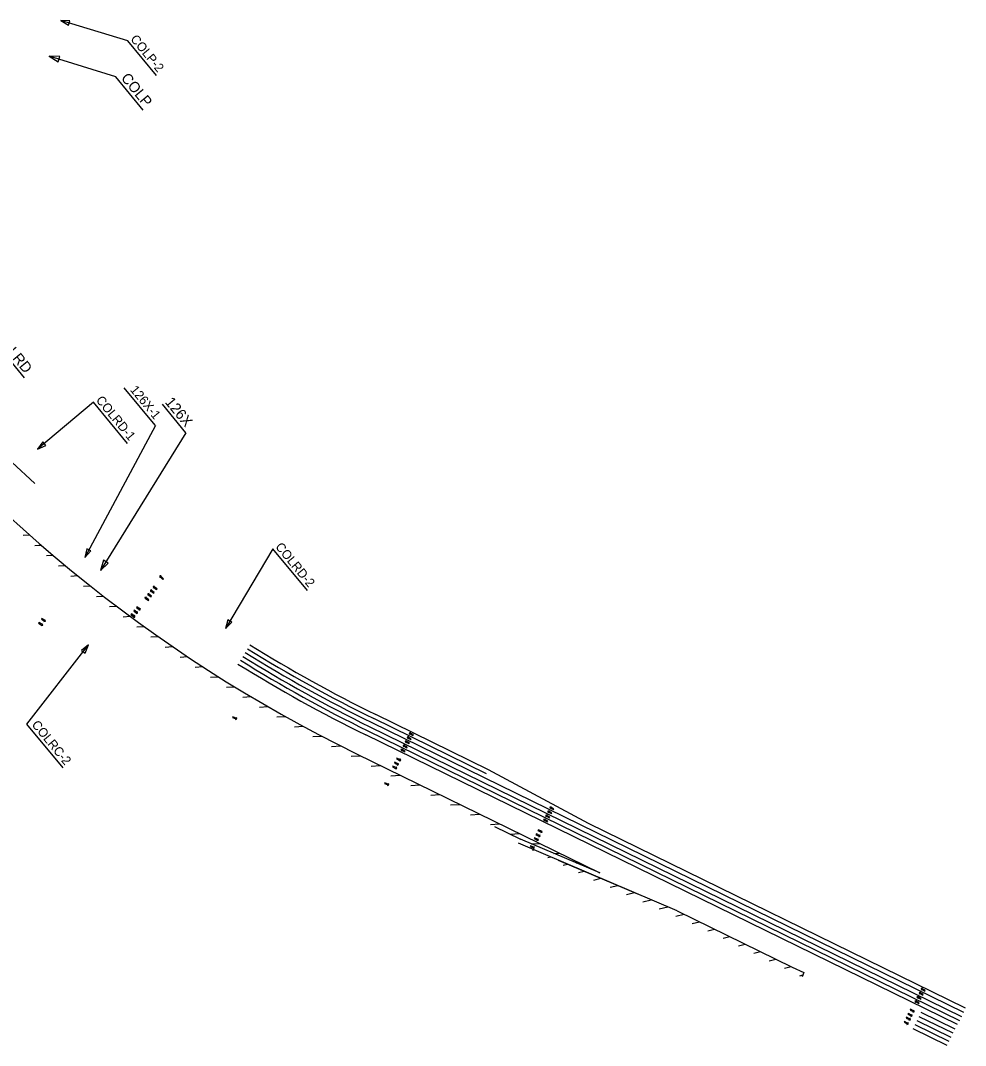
# Model space of a CAD drawing. Extents: x 1966356 to 1974207, y 790684 to 800034.
# Drawn here: x 1971705 to 1974207, y 793957 to 796672 of the extents above; entities that cross this region are included whole.
import ezdxf

# ---------------------------------------------------------------- set-up
doc = ezdxf.new("R2010")
doc.units = 0
for name, color, linetype in [('RD_EX_Pavement_Markings', 7, 'Continuous'), ('RD_PD_ALT5_LnLine', 7, 'Continuous'), ('RD_TX_RoadID', 7, 'Continuous')]:
    doc.layers.add(name, color=color, linetype=linetype)

msp = doc.modelspace()

# ---------------------------------------------------------------- linework, layer by layer
at = {"layer": 'RD_EX_Pavement_Markings'}
for p, q in [((1972944.6, 794687.2), (1972645.7, 794833.6)), ((1972635.1, 794812), (1974201.9, 794044.9)), ((1972939.3, 794676.4), (1972640.4, 794822.8)), ((1974186, 794012.5), (1972619.3, 794779.7)), ((1972624.6, 794790.5), (1974191.3, 794023.3)), ((1972629.9, 794801.2), (1974196.6, 794034.1)), ((1973208.8, 794544.5), (1972944.6, 794687.2)), ((1974207.1, 794055.6), (1973208.8, 794544.5)), ((1974169.3, 793978.4), (1974079.5, 794022.4)), ((1974174.6, 793989.2), (1974084.8, 794033.2)), ((1974179.9, 794000), (1974090.1, 794043.9)), ((1974158.8, 793956.9), (1974069, 794000.8)), ((1974164, 793967.6), (1974074.2, 794011.6))]:
    msp.add_line(p, q, dxfattribs=at)
for radius in [3776.7, 3764.7, 3752.7, 3800.7, 3788.7, 3812.7]:
    msp.add_arc((1974296, 798203.9), radius, 238.0979, 243.9112, dxfattribs=at)
at = {"layer": 'RD_PD_ALT5_LnLine'}
for p, q in [((1971712.1, 795308.5), (1971729, 795309.5)), ((1971742.9, 795281.3), (1971760, 795282.4)), ((1971774.3, 795254.2), (1971791.5, 795255.3)), ((1971806.3, 795227.1), (1971823.7, 795228.2)), ((1971839, 795200.1), (1971856.6, 795201.2)), ((1971872.4, 795173.1), (1971890.2, 795174.2)), ((1971906.4, 795146.2), (1971924.5, 795147.3)), ((1971941.3, 795119.3), (1971959.6, 795120.4)), ((1971976.9, 795092.4), (1971995.5, 795093.6)), ((1972013.3, 795065.6), (1972032.1, 795066.8)), ((1972050.5, 795038.8), (1972069.6, 795040)), ((1972088.6, 795012.1), (1972108.1, 795013.3)), ((1972127.7, 794985.5), (1972147.4, 794986.7)), ((1972167.7, 794958.9), (1972187.7, 794960.2)), ((1972208.7, 794932.4), (1972229.1, 794933.7)), ((1972250.7, 794905.9), (1972271.5, 794907.2)), ((1972293.9, 794879.6), (1972315.1, 794880.9)), ((1972338.3, 794853.2), (1972359.8, 794854.6)), ((1972383.9, 794827), (1972405.9, 794828.4)), ((1972430.8, 794800.8), (1972453.3, 794802.2)), ((1972479.2, 794774.8), (1972502.2, 794776.2)), ((1972529.1, 794748.8), (1972552.7, 794750.3)), ((1972594.7, 794729.4), (1973239.1, 794413.9)), ((1972580.6, 794722.9), (1972604.8, 794724.4)), ((1972633.3, 794697.1), (1972657.5, 794698.6)), ((1972686, 794671.3), (1972710.2, 794672.8)), ((1972738.6, 794645.5), (1972762.9, 794647)), ((1972791.3, 794619.7), (1972815.6, 794621.2)), ((1972844, 794593.9), (1972868.3, 794595.4)), ((1972896.7, 794568.1), (1972920.9, 794569.6)), ((1972949.4, 794542.3), (1972973.6, 794543.8)), ((1972960.6, 794536.9), (1973028.9, 794503.4)), ((1973002.1, 794516.5), (1973026.3, 794518)), ((1973444.2, 794313.4), (1973024, 794492.5)), ((1973239.1, 794413.9), (1973028.7, 794503.5)), ((1973058.1, 794490.9), (1973079, 794492.2)), ((1973061.1, 794474.3), (1973064.6, 794475.1)), ((1973101.6, 794454.4), (1973109, 794456.2)), ((1973117.7, 794465.6), (1973131.7, 794466.4)), ((1973129, 794447.7), (1973339.2, 794358.2)), ((1973142.2, 794434.6), (1973153.3, 794437.4)), ((1973177.3, 794440.2), (1973184.4, 794440.6)), ((1973182.7, 794414.8), (1973197.7, 794418.5)), ((1973223.2, 794394.9), (1973242, 794399.6)), ((1973236.8, 794414.8), (1973237.1, 794414.8)), ((1973266.5, 794375.8), (1973286.4, 794380.7)), ((1973309.9, 794356.6), (1973330.7, 794361.8)), ((1973353.2, 794337.5), (1973375, 794342.9)), ((1973396.6, 794318.4), (1973419.4, 794324)), ((1973440, 794299.2), (1973462, 794304.7)), ((1973444.2, 794313.4), (1973748.5, 794164.4)), ((1973483.4, 794280.1), (1973502.6, 794284.8)), ((1973525, 794260.5), (1973543.1, 794265)), ((1973565.5, 794240.7), (1973583.6, 794245.2)), ((1973606, 794220.8), (1973624.1, 794225.3)), ((1973646.5, 794201), (1973664.6, 794205.5)), ((1973687, 794181.2), (1973705.2, 794185.6)), ((1973727.6, 794161.3), (1973745.7, 794165.8)), ((1973748.5, 794164.4), (1973779.6, 794149.8)), ((1973768.8, 794141.6), (1973776.7, 794143.6)), ((1973779.6, 794149.8), (1973774.5, 794138.9))]:
    msp.add_line(p, q, dxfattribs=at)
for points in [[(1972082, 795191.4), (1972083.7, 795193.1), (1972077.1, 795199.5), (1972078.2, 795200.7), (1972074.2, 795200.6), (1972074.3, 795196.6), (1972075.4, 795197.8)], [(1972058.3, 795154.8), (1972059.7, 795156.7), (1972052.3, 795162.2), (1972053.3, 795163.5), (1972049.3, 795162.9), (1972049.9, 795158.9), (1972050.9, 795160.2)], [(1972065.5, 795164.2), (1972066.9, 795166.1), (1972059.5, 795171.6), (1972060.5, 795172.9), (1972056.5, 795172.3), (1972057.1, 795168.3), (1972058.1, 795169.6)], [(1972043.9, 795135.3), (1972045.3, 795137.2), (1972037.9, 795142.7), (1972038.9, 795144), (1972034.9, 795143.4), (1972035.5, 795139.4), (1972036.5, 795140.7)], [(1972051, 795145.1), (1972052.4, 795147.1), (1972045.1, 795152.5), (1972046, 795153.8), (1972042.1, 795153.2), (1972042.7, 795149.3), (1972043.6, 795150.6)], [(1972006.4, 795109.7), (1972005, 795107.8), (1972012.3, 795102.3), (1972011.4, 795101), (1972015.3, 795101.6), (1972014.7, 795105.6), (1972013.8, 795104.3)], [(1972013.7, 795119), (1972012.3, 795117.1), (1972019.7, 795111.6), (1972018.7, 795110.3), (1972022.6, 795110.9), (1972022, 795114.9), (1972021.1, 795113.6)], [(1971754.7, 795077.4), (1971753.4, 795075.4), (1971761.1, 795070.4), (1971760.2, 795069), (1971764.1, 795069.8), (1971763.3, 795073.8), (1971762.4, 795072.4)], [(1971762.2, 795088.1), (1971760.8, 795086.1), (1971768.5, 795081.1), (1971767.6, 795079.7), (1971771.5, 795080.5), (1971770.7, 795084.4), (1971769.8, 795083.1)], [(1971999.3, 795099.8), (1971997.9, 795097.9), (1972005.3, 795092.5), (1972004.3, 795091.2), (1972008.3, 795091.7), (1972007.7, 795095.7), (1972006.7, 795094.4)], [(1972267.7, 794827.5), (1972266.8, 794825.3), (1972275.2, 794821.7), (1972274.6, 794820.2), (1972278.3, 794821.7), (1972276.8, 794825.4), (1972276.2, 794823.9)], [(1972744.4, 794778.1), (1972745.4, 794780.2), (1972737.2, 794784.3), (1972737.9, 794785.7), (1972734.1, 794784.4), (1972735.4, 794780.6), (1972736.1, 794782.1)], [(1972728.3, 794745.3), (1972729.4, 794747.5), (1972721.1, 794751.5), (1972721.8, 794753), (1972718.1, 794751.7), (1972719.4, 794747.9), (1972720.1, 794749.3)], [(1972733.7, 794756.4), (1972734.8, 794758.5), (1972726.5, 794762.6), (1972727.3, 794764), (1972723.5, 794762.7), (1972724.8, 794759), (1972725.5, 794760.4)], [(1972739, 794767.1), (1972740, 794769.3), (1972731.8, 794773.3), (1972732.5, 794774.8), (1972728.7, 794773.5), (1972730, 794769.7), (1972730.8, 794771.2)], [(1972723, 794734.4), (1972724, 794736.6), (1972715.8, 794740.6), (1972716.5, 794742.1), (1972712.7, 794740.8), (1972714, 794737), (1972714.7, 794738.4)], [(1972696.3, 794707.2), (1972695.2, 794705), (1972703.5, 794701), (1972702.8, 794699.5), (1972706.5, 794700.8), (1972705.2, 794704.6), (1972704.5, 794703.2)], [(1972701.7, 794718.2), (1972700.6, 794716.1), (1972708.9, 794712.1), (1972708.2, 794710.6), (1972712, 794711.9), (1972710.7, 794715.7), (1972709.9, 794714.2)], [(1972691.4, 794697.1), (1972690.3, 794695), (1972698.5, 794690.9), (1972697.8, 794689.5), (1972701.6, 794690.8), (1972700.3, 794694.6), (1972699.6, 794693.1)], [(1972670.2, 794652.8), (1972669.3, 794650.6), (1972677.7, 794647), (1972677.1, 794645.5), (1972680.8, 794647), (1972679.3, 794650.7), (1972678.7, 794649.2)], [(1973116.5, 794581.7), (1973117.6, 794583.9), (1973109.3, 794587.9), (1973110, 794589.3), (1973106.3, 794588.1), (1973107.5, 794584.3), (1973108.3, 794585.7)], [(1973105.8, 794559.9), (1973106.9, 794562), (1973098.6, 794566.1), (1973099.4, 794567.5), (1973095.6, 794566.2), (1973096.9, 794562.4), (1973097.6, 794563.9)], [(1973111.2, 794571), (1973112.3, 794573.1), (1973104.1, 794577.1), (1973104.8, 794578.6), (1973101, 794577.3), (1973102.3, 794573.5), (1973103, 794575)], [(1973100.5, 794549), (1973101.5, 794551.1), (1973093.3, 794555.2), (1973094, 794556.6), (1973090.2, 794555.3), (1973091.5, 794551.5), (1973092.2, 794553)], [(1973071.1, 794517.3), (1973070, 794515.1), (1973078.3, 794511.1), (1973077.5, 794509.6), (1973081.3, 794510.9), (1973080, 794514.7), (1973079.3, 794513.3)], [(1973076.5, 794528.3), (1973075.4, 794526.2), (1973083.7, 794522.1), (1973083, 794520.7), (1973086.7, 794522), (1973085.4, 794525.8), (1973084.7, 794524.3)], [(1973055.6, 794486), (1973054.7, 794483.8), (1973063.1, 794480.2), (1973062.5, 794478.7), (1973066.2, 794480.2), (1973064.7, 794483.9), (1973064, 794482.4)], [(1973066.1, 794507.2), (1973065.1, 794505.1), (1973073.3, 794501), (1973072.6, 794499.6), (1973076.4, 794500.9), (1973075.1, 794504.6), (1973074.4, 794503.2)], [(1974099.7, 794101.1), (1974100.7, 794103.2), (1974092.5, 794107.3), (1974093.2, 794108.7), (1974089.4, 794107.4), (1974090.7, 794103.6), (1974091.4, 794105.1)], [(1974083.6, 794068.3), (1974084.7, 794070.5), (1974076.5, 794074.5), (1974077.2, 794076), (1974073.4, 794074.7), (1974074.7, 794070.9), (1974075.4, 794072.4)], [(1974089, 794079.3), (1974090, 794081.4), (1974081.8, 794085.4), (1974082.5, 794086.9), (1974078.7, 794085.6), (1974080, 794081.8), (1974080.7, 794083.3)], [(1974094.4, 794090.3), (1974095.5, 794092.5), (1974087.2, 794096.5), (1974087.9, 794098), (1974084.2, 794096.7), (1974085.5, 794092.9), (1974086.2, 794094.4)], [(1974061.4, 794052.7), (1974060.3, 794050.5), (1974068.6, 794046.5), (1974067.9, 794045), (1974071.6, 794046.3), (1974070.3, 794050.1), (1974069.6, 794048.6)], [(1974045.6, 794020.4), (1974044.5, 794018.3), (1974052.8, 794014.2), (1974052.1, 794012.8), (1974055.9, 794014.1), (1974054.6, 794017.9), (1974053.8, 794016.4)], [(1974051.1, 794031.6), (1974050, 794029.4), (1974058.2, 794025.4), (1974057.5, 794023.9), (1974061.3, 794025.2), (1974060, 794029), (1974059.3, 794027.5)], [(1974056, 794041.6), (1974054.9, 794039.5), (1974063.2, 794035.4), (1974062.4, 794034), (1974066.2, 794035.3), (1974064.9, 794039.1), (1974064.2, 794037.6)]]:
    msp.add_lwpolyline(points, close=True, dxfattribs=at)
for radius, start, end in [(3868.7, 217.2903, 243.9112), (3758.7, 223.1722, 227.2191)]:
    msp.add_arc((1974296, 798203.9), radius, start, end, dxfattribs=at)
at = {"layer": 'RD_TX_RoadID'}
for p, q in [((1972065.1, 796526), (1971989.6, 796617.4)), ((1972030.3, 796434.4), (1971957.9, 796522)), ((1971716.1, 795724.9), (1971628.4, 795831.1)), ((1972061.9, 795599.8), (1971979.9, 795699.1)), ((1971988.8, 795551.5), (1971898.4, 795661)), ((1972143.4, 795579.8), (1972080.9, 795655.6)), ((1972465, 795161.5), (1972373.3, 795272.6)), ((1971818.6, 794692), (1971722.5, 794808.3))]:
    msp.add_line(p, q, dxfattribs=at)
for points in [[(1971989.6, 796617.4), (1971811.8, 796671.5)], [(1971957.9, 796522), (1971781.4, 796577.5)], [(1971898.4, 795661), (1971750.6, 795536)], [(1972062.6, 795598.8), (1971875.3, 795249.2)], [(1972143.4, 795579.8), (1971917.3, 795215.3)], [(1972373.3, 795272.6), (1972247.9, 795061.4)], [(1971722.5, 794808.3), (1971885.7, 795017.8)]]:
    msp.add_lwpolyline(points, dxfattribs=at)
for points in [[(1971835.8, 796670.7), (1971811.8, 796671.5), (1971832.1, 796658.8)], [(1971809.4, 796576.3), (1971781.4, 796577.5), (1971805.1, 796562.5)], [(1971764.3, 795555.7), (1971750.6, 795536), (1971772.3, 795546.2)], [(1971880.8, 795272.5), (1971875.3, 795249.2), (1971891.8, 795266.7)], [(1971925.4, 795242.1), (1971917.3, 795215.3), (1971937.7, 795234.5)], [(1972254.4, 795084.5), (1972247.9, 795061.4), (1972265.1, 795078.2)], [(1971876.4, 794995.7), (1971885.7, 795017.8), (1971866.6, 795003.3)]]:
    msp.add_lwpolyline(points, close=True, dxfattribs=at)

# ---------------------------------------------------------------- texts
for s, height, p in [('COLP-2', 24, (1971995, 796621.8)), (' COLP', 28, (1971963.3, 796526.5)), ('COLRD', 28, (1971633.8, 795835.6)), ('126X-1', 24, (1971994.2, 795692.7)), ('COLRD-1', 24, (1971903.8, 795665.4)), ('126X ', 28, (1972086.3, 795660.1)), ('COLRD-2', 24, (1972378.7, 795277)), (' COLRC-2', 24, (1971727.9, 794812.8))]:
    msp.add_text(s, height=height, rotation=309.5517, dxfattribs=at).set_placement(p)

doc.saveas('drawing.dxf')
